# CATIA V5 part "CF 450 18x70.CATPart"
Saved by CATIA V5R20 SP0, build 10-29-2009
Part number: CF 450 18x70
Definition: NONE
Nomenclature: CF 450 18x70
Source: Unknown
Description: CF 450 18x70
Bounding box of the stored display mesh (mm): x -17 to 17, y 0 to 70, z -17 to 17
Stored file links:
  C:\Users\Utente\Desktop\IO LAVORO\3D X SITO CF\X SITO\CF 450\CF 450 18x70.CATPart
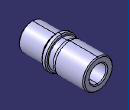
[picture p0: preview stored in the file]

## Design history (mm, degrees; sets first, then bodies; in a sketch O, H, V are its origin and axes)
Body1 "Rivoluzione1" (main body)
  Solid1: solid without history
